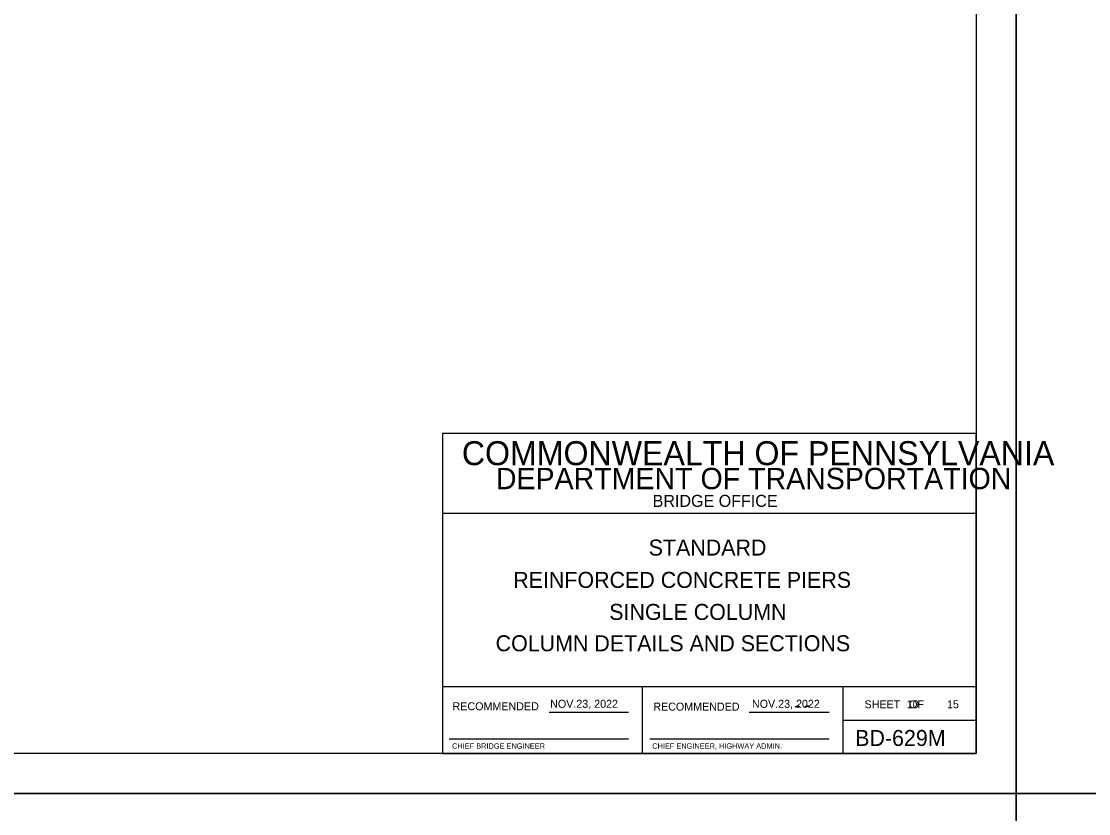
# Model space of a CAD drawing. Extents: x 646165 to 651486, y 296916 to 299292.
# Drawn here: x 650257.8 to 650657.7, y 298096.8 to 298393.8 of the extents above; entities that cross this region are included whole.
import ezdxf

# ---------------------------------------------------------------- set-up
doc = ezdxf.new("R2010")
doc.units = 0
for name, color, linetype in [('2', 7, 'Continuous'), ('60', 7, 'Continuous'), ('DATES', 7, 'Continuous'), ('PLT-BNDY', 7, 'Continuous'), ('SIGNATORY TITLES', 7, 'Continuous')]:
    doc.layers.add(name, color=color, linetype=linetype)

msp = doc.modelspace()

# ---------------------------------------------------------------- linework, layer by layer
at = {"layer": '2'}
for p, q in [((650615.59, 298683.25), (650615.59, 298119.25)), ((650615.59, 298239.25), (650415.59, 298239.25)), ((650415.59, 298239.25), (650415.59, 298119.25)), ((650615.59, 298119.25), (650615.59, 298239.25)), ((650615.59, 298209.25), (650415.59, 298209.25)), ((650615.59, 298144.25), (650415.59, 298144.25)), ((650490.59, 298119.25), (650490.59, 298144.25)), ((650565.59, 298144.25), (650565.59, 298119.25)), ((650455.56, 298134.75), (650485.32, 298134.75)), ((650530.56, 298134.75), (650560.46, 298134.75)), ((650565.59, 298131.75), (650615.59, 298131.75)), ((650418.09, 298124.75), (650485.32, 298124.75)), ((650493.22, 298124.75), (650560.46, 298124.75)), ((650615.59, 298119.25), (649829.59, 298119.25)), ((650415.59, 298119.25), (650615.59, 298119.25))]:
    msp.add_line(p, q, dxfattribs=at)
at = {"layer": '60'}
for points in [[(650547.78, 298136.84), (650548.75, 298137.18), (650549.46, 298136.85)], [(650551.39, 298136.84), (650551.84, 298137.21), (650552.67, 298137.16), (650552.81, 298136.83), (650552.28, 298136.86)]]:
    msp.add_lwpolyline(points, close=True, dxfattribs=at)
at = {"layer": 'PLT-BNDY'}
for points in [[(649789.59, 298698.25), (650630.59, 298698.25), (650630.59, 298104.25), (649789.59, 298104.25)], [(650630.59, 298698.25), (651471.59, 298698.25), (651471.59, 298104.25), (650630.59, 298104.25)], [(649789.59, 298104.25), (650630.59, 298104.25), (650630.59, 297510.25), (649789.59, 297510.25)], [(650630.59, 298104.25), (651471.59, 298104.25), (651471.59, 297510.25), (650630.59, 297510.25)]]:
    msp.add_lwpolyline(points, close=True, dxfattribs=at)

# ---------------------------------------------------------------- texts
at = {"layer": '2'}
for s, height, p in [('COMMONWEALTH OF PENNSYLVANIA', 9, (650422.84, 298227.38)), ('DEPARTMENT OF TRANSPORTATION', 8.0003, (650435.59, 298218.38)), ('BRIDGE OFFICE', 4.5, (650494.34, 298211.75)), ('STANDARD', 6, (650492.84, 298193.5)), ('REINFORCED CONCRETE PIERS', 6, (650442.09, 298181.38)), ('SINGLE COLUMN', 6, (650478.07, 298169.37)), ('COLUMN DETAILS AND SECTIONS', 6, (650435.5, 298157.62)), ('SHEET   OF  ', 3, (650573.72, 298136.25)), ('10', 3, (650589.56, 298136.25)), ('15', 3, (650604.64, 298136.25)), ('BD-629M', 6, (650570.22, 298122.12))]:
    msp.add_text(s, height=height, dxfattribs=at).set_placement(p)
for p in [(650419.36, 298135.5), (650494.58, 298135.37)]:
    msp.add_text('RECOMMENDED', height=3, rotation=360, dxfattribs=at).set_placement(p)
at = {"layer": 'DATES'}
for p in [(650455.93, 298136.43), (650531.55, 298136.43)]:
    msp.add_text('NOV.23, 2022', height=3, dxfattribs=at).set_placement(p)
at = {"layer": 'SIGNATORY TITLES'}
for s, p in [('CHIEF BRIDGE ENGINEER', (650419.18, 298121.12)), ('CHIEF ENGINEER, HIGHWAY ADMIN.', (650494.18, 298121.12))]:
    msp.add_text(s, height=2, dxfattribs=at).set_placement(p)

doc.saveas('drawing.dxf')
